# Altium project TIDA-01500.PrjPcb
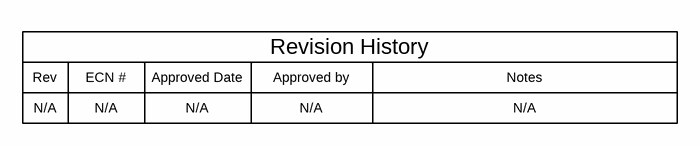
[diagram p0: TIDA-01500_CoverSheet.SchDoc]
CopyrightYear: 2017; PCB_Layout: Levan Bidzishvili; PCB_Rev: E1; PRJ_Customer: Public Release; PRJ_Engineer: Levan Bidzishvili; PRJ_Number: TIDA-01500; PRJ_Title: Automotive Multi Channel LED Driver for HVAC HMI; SCH_Rev: E1; TechSupport: http://www.ti.com/support; TID: N/A
3 sheets, 58 parts. Net scope: global (net labels, ports and power ports of the same name join across sheets).
Board file: TIDA-01500_PCB.PcbDoc
Sheets:
  TIDA-01500_CoverSheet.SchDoc
  TIDA-01500_BlankSheet.SchDoc
  TIDA-01500_EVM_Hardware.SchDoc

## Sheet TIDA-01500_CoverSheet.SchDoc
size 431 x 279 mm; Date: Not shown in title block; ApprovedBy: Not shown in title block; CheckedBy: Not shown in title block; Author: Not shown in title block; CompanyName: Not shown in title block; Engineer: Not shown in title block; Organization: Not shown in title block; Address1: Not shown in title block; Address2: Not shown in title block; Address3: Not shown in title block; Address4: Not shown in title block; DocumentNumber: 1; Revision: Use project parameter SCH_Rev; SheetNumber: 1; SheetTotal: 3; PageSetup: Record=PageOptions¦CenterHorizontal=True¦CenterVertical=True¦PrintScale=1.00¦XCorrection=1.00¦YCorrection=1.00¦PrintKind=0¦BorderSize=5000000¦LeftOffset=0¦BottomOffset=0¦Orientation=2¦PaperLength=1000¦PaperWidth=1000¦Scale=100¦PaperSource=15¦PrintQuality=600¦MediaType=1¦DitherType=10¦PaperKind=Letter¦PrintScaleMode=1

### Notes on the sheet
- Rev
- N/A
- ECN #
- Approved Date
- Approved by
- Revision History
- Notes

## Sheet TIDA-01500_BlankSheet.SchDoc
size 431 x 279 mm; Date: Not shown in title block; ApprovedBy: Not shown in title block; CheckedBy: Not shown in title block; Author: Not shown in title block; CompanyName: Not shown in title block; Engineer: Not shown in title block; Organization: Not shown in title block; Address1: Not shown in title block; Address2: Not shown in title block; Address3: Not shown in title block; Address4: Not shown in title block; DocumentNumber: 1; Revision: Use project parameter SCH_Rev; SheetNumber: 2; SheetTotal: 3; PageSetup: Record=PageOptions¦CenterHorizontal=True¦CenterVertical=True¦PrintScale=0.64¦XCorrection=1.00¦YCorrection=1.00¦PrintKind=0¦BorderSize=5000000¦LeftOffset=0¦BottomOffset=0¦Orientation=2¦PaperLength=1000¦PaperWidth=1000¦Scale=100¦PaperSource=15¦PrintQuality=600¦MediaType=1¦DitherType=10¦PrintScaleMode=1¦PaperKind=Letter
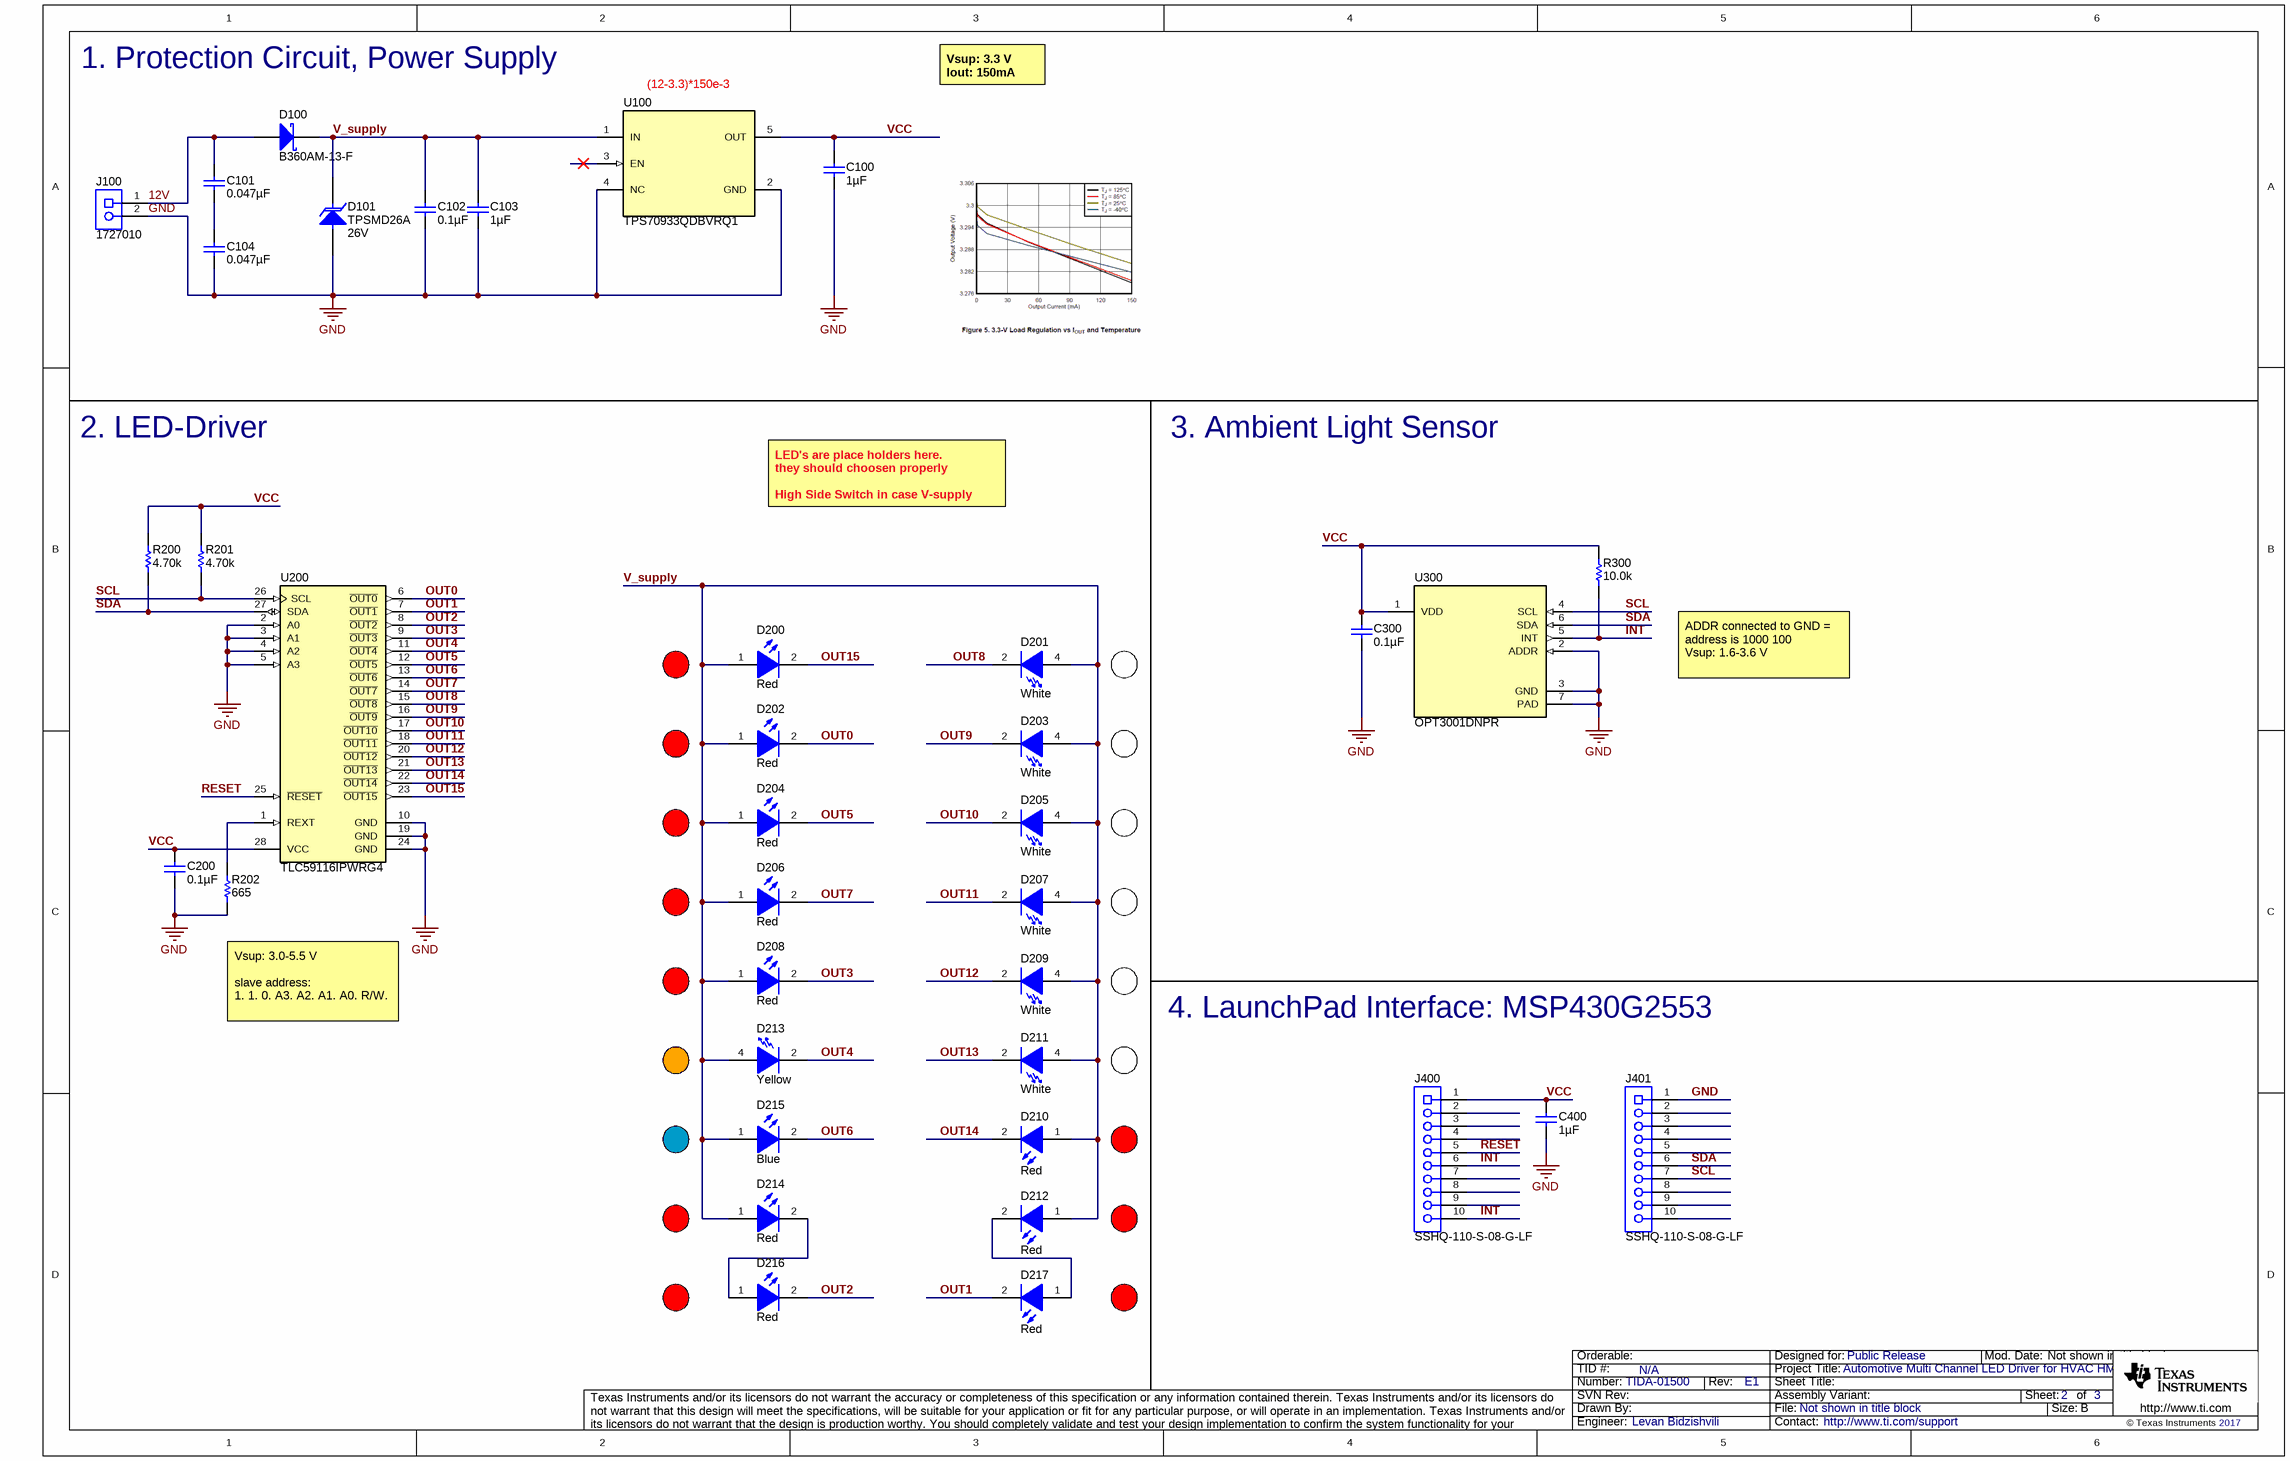
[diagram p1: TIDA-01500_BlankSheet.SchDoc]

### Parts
C100  ValueDisplayed: 1µF  [0805_HV]  (hidden comment: CGA4J3X7R1H105K125AB)
C101  ValueDisplayed: 0.047µF  [0805_HV]  (hidden comment: GCM21BR72A473KA37L)
C102  ValueDisplayed: 0.1µF  [0805_HV]  (hidden comment: GCM21BR71H104KA37K)
C103  ValueDisplayed: 1µF  [0805_HV]  (hidden comment: CGA4J3X7R1H105K125AB)
C104  ValueDisplayed: 0.047µF  [0805_HV]  (hidden comment: GCM21BR72A473KA37L)
C200  ValueDisplayed: 0.1µF  [0805_HV]  (hidden comment: GCM21BR71H104KA37K)
C300  ValueDisplayed: 0.1µF  [0603]  (hidden comment: CGJ3E2X7R1C104K080AA)
C400  ValueDisplayed: 1µF  [0805_HV]  (hidden comment: CGA4J3X7R1H105K125AB)
D100  B360AM-13-F  [SMA]
D101  TPSMD26A  value 26V  [SMC_265]
D200  value Red  [VLMR334_Red]  (hidden comment: VLMR334BACB-GS08)
D201  value White  [LED_PowerTOPLED_GF]  (hidden comment: LW-E6SG)
D202  value Red  [VLMR334_Red]  (hidden comment: VLMR334BACB-GS08)
D203  value White  [LED_PowerTOPLED_GF]  (hidden comment: LW-E6SG)
D204  value Red  [VLMR334_Red]  (hidden comment: VLMR334BACB-GS08)
D205  value White  [LED_PowerTOPLED_GF]  (hidden comment: LW-E6SG)
D206  value Red  [VLMR334_Red]  (hidden comment: VLMR334BACB-GS08)
D207  value White  [LED_PowerTOPLED_GF]  (hidden comment: LW-E6SG)
D208  value Red  [VLMR334_Red]  (hidden comment: VLMR334BACB-GS08)
D209  value White  [LED_PowerTOPLED_GF]  (hidden comment: LW-E6SG)
D210  value Red  [VLMR334_Red]  (hidden comment: VLMR334BACB-GS08)
D211  value White  [LED_PowerTOPLED_GF]  (hidden comment: LW-E6SG)
D212  value Red  [VLMR334_Red]  (hidden comment: VLMR334BACB-GS08)
D213  value Yellow  [LED_PowerTOPLED_GF]  (hidden comment: LY-E6SF)
D214  value Red  [VLMR334_Red]  (hidden comment: VLMR334BACB-GS08)
D215  value Blue  [LB_T673_Blue]  (hidden comment: LB T673-L2P1-25-Z)
D216  value Red  [VLMR334_Red]  (hidden comment: VLMR334BACB-GS08)
D217  value Red  [VLMR334_Red]  (hidden comment: VLMR334BACB-GS08)
J100  1727010  [PhoenixConact_1727010]
J400  SSHQ-110-S-08-G-LF  [Major_SSHQ-110-S-08]
J401  SSHQ-110-S-08-G-LF  [Major_SSHQ-110-S-08]
R200  ValueDisplayed: 4.70k  [0805_HV]  (hidden comment: ERJ-P06F4701V)
R201  ValueDisplayed: 4.70k  [0805_HV]  (hidden comment: ERJ-P06F4701V)
R202  ValueDisplayed: 665  [0805_HV]  (hidden comment: ERA-6AEB6650V)
R300  ValueDisplayed: 10.0k  [TNPW0603]  (hidden comment: TNPW060310K0BEEA)
U100  TPS70933QDBVRQ1  [DBV0005A_N]
U200  TLC59116IPWRG4  [PW0028A_N]
U300  OPT3001DNPR  [DNP0006A]

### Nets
GND: C100.2 C102.2 C103.2 C104.2 C200.2 C300.2 C400.2 D101.2(A) J100.2 J401.1 R202.1 U100.2(GND) U100.4(NC) U200.2(A0) U200.3(A1) U200.4(A2) U200.5(A3) U200.10(GND) U200.19(GND) U200.24(GND) U300.2(ADDR) U300.3(GND) U300.7(PAD)
12V: C101.1 D100.2(A) J100.1
INT: J400.6 J400.10 R300.2 U300.5(INT)
OUT0: D202.2(K) U200.6(~{OUT0})
OUT1: D217.2(K) U200.7(~{OUT1})
OUT2: D216.2(K) U200.8(~{OUT2})
OUT3: D208.2(K) U200.9(~{OUT3})
OUT4: D213.2(K) U200.11(~{OUT4})
OUT5: D204.2(K) U200.12(~{OUT5})
OUT6: D215.2(K) U200.13(~{OUT6})
OUT7: D206.2(K) U200.14(~{OUT7})
OUT8: D201.2(K) U200.15(~{OUT8})
OUT9: D203.2(K) U200.16(~{OUT9})
OUT10: D205.2(K) U200.17(~{OUT10})
OUT11: D207.2(K) U200.18(~{OUT11})
OUT12: D209.2(K) U200.20(~{OUT12})
OUT13: D211.2(K) U200.21(~{OUT13})
OUT14: D210.2(K) U200.22(~{OUT14})
OUT15: D200.2(K) U200.23(~{OUT15})
RESET: J400.5 U200.25(~{RESET})
SCL: J401.7 R201.1 U200.26(SCL) U300.4(SCL)
SDA: J401.6 R200.1 U200.27(SDA) U300.6(SDA)
V_supply: C102.1 C103.1 D100.1(K) D101.1(K) D200.1(A) D201.4(A) D202.1(A) D203.4(A) D204.1(A) D205.4(A) D206.1(A) D207.4(A) D208.1(A) D209.4(A) D210.1(A) D211.4(A) D212.1(A) D213.4(A) D214.1(A) D215.1(A) U100.1(IN)
VCC: C100.1 C200.1 C300.1 C400.1 J400.1 R200.2 R201.2 R300.1 U100.5(OUT) U200.28(VCC) U300.1(VDD)
NetC101_2: C101.2 C104.1
NetD212_2: D212.2(K) D217.1(A)
NetD214_2: D214.2(K) D216.1(A)
NetR202_2: R202.2 U200.1(REXT)

Not connected (* = marked no-connect by the designer): J400 2 3 4 7 8 9; J401 2 3 4 5 8 9 10; U100 3(EN)*

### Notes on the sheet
- 1. Protection Circuit, Power Supply
- (near U100) (12-3.3)*150e-3
- Vsup: 3.3 V
  Iout: 150mA
- standoff voltage should be above 24V because of jump-start condition. better would be 26V
  SMAJ26CAHE3/61 VISHAY
  TPS... littlefuse
- 2. LED-Driver
- 3. Ambient Light Sensor
- LED's are place holders here.
  they should choosen properly
  High Side Switch in case V-supply goes above 17V
- ADDR connected to GND = address is 1000 100
  Vsup: 1.6-3.6 V
- (near R202) Vsup: 3.0-5.5 V
  slave address:
  1. 1. 0. A3. A2. A1. A0. R/W.
- 4. LaunchPad Interface: MSP430G2553
- ToDo:
  1) LaunchPad supply
  2) some editional features like buttons
  3) high side switch to On/Off LED voltage in case Vsupply goes over 17V
  4) choosing the propper LED's

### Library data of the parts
C100 C103 C400 = CGA4J3X7R1H105K125AB: CAP, CERM, 1 µF, 50 V, +/- 10%, X7R, AEC-Q200 Grade 1, 0805; Manufacturer: TDK; Polarized: N; CompType: Capacitor; Value: 1uF; U/M: EA; Cap_F: 0.000001; Tolerance_%: 10; ESR_ohm: 0.008782; Value1: 0.008782 ohm; VDC_V: 50; Value2: 50V; IRMS_A: 2.20488; TaMin_C: -55; TaMax_C: 125; Cap_Case: 0805; SizeArea_mm2: 2.5; SizeAreaWB_mm2: 6.75; SizeX_mm: 2; SizeY_mm: 1.25; SizeZ_mm: 1.45; AEC Category: Q200; AEC Qualified: Y; AEC Grade: 1
C101 C104 = GCM21BR72A473KA37L: CAP, CERM, 0.047 µF, 100 V, +/- 10%, X7R, AEC-Q200 Grade 1, 0805; Manufacturer: MuRata; Polarized: N; CompType: Capacitor; Value: 0.047uF; U/M: EA; Cap_F: 0.000000047; Tolerance_%: 10; Value1: Unknown; VDC_V: 100; Value2: 100V; TaMin_C: -55; TaMax_C: 125; Cap_Case: 0805; SizeArea_mm2: 2.5; SizeAreaWB_mm2: 6.75; SizeX_mm: 2; SizeY_mm: 1.25; SizeZ_mm: 1.45; AEC Category: Q200; AEC Qualified: Y; AEC Grade: 1
C102 C200 = GCM21BR71H104KA37K: CAP, CERM, 0.1 µF, 50 V, +/- 10%, X7R, AEC-Q200 Grade 1, 0805; Manufacturer: MuRata; Polarized: N; CompType: Capacitor; Value: 0.1uF; U/M: EA; Cap_F: 0.0000001; Tolerance_%: 10; Value1: Unknown; VDC_V: 50; Value2: 50V; TaMin_C: -55; TaMax_C: 125; Cap_Case: 0805; SizeArea_mm2: 2.5; SizeAreaWB_mm2: 6.75; SizeX_mm: 2; SizeY_mm: 1.25; SizeZ_mm: 1.45; AEC Category: Q200; AEC Qualified: Y; AEC Grade: 1
C300 = CGJ3E2X7R1C104K080AA: CAP, CERM, 0.1 µF, 16 V,+/- 10%, X7R, AEC-Q200 Grade 1, 0603; Manufacturer: TDK; Polarized: N; CompType: Capacitor; Value: 0.1uF; U/M: EA; Cap_F: 0.0000001; Tolerance_%: 10; VDC_V: 16; Value2: 16V; TaMin_C: -55; TaMax_C: 125; SizeArea_mm2: 1.28; SizeAreaWB_mm2: 4.68; SizeX_mm: 1.6; SizeY_mm: 0.8; SizeZ_mm: 1; AEC Category: Q200; AEC Qualified: Y; Green_Lifecycle: NRND; Green_REACh: Passed
D100 = B360AM-13-F: Diode, Schottky, 60 V, 3 A, AEC-Q101, SMA; Manufacturer: Diodes Inc.; U/M: EA; Vf_V: 0.7; Value: 60V; Value1: 3A; Value2: 0.7V; Io_A: 3; Vr_V: 60; TJmax_C: 150; SizeAreaWB_mm2: 37.3428; SizeArea_mm2: 16.3228; SizeX_mm: 5.59; SizeY_mm: 2.92; SizeZ_mm: 2.87; AEC Category: Q101; AEC Qualified: Y; Green_Lifecycle: Not Set; Green_REACh: Incomplete
D101 = TPSMD26A: Diode, TVS, Uni, 26 V, 42.1 Vc, AEC-Q101, SMC; Manufacturer: Littelfuse; U/M: EA; Power_W: 6.5; Vr_V: 26; Value1: 6.5W; RJA_CperW: 75; SizeAreaWB_mm2: 78.5757; SizeArea_mm2: 46.8857; SizeX_mm: 7.94; SizeY_mm: 5.905; SizeZ_mm: 2.62; AEC Category: Q101; AEC Qualified: Y
D200 D202 D204 D206 D208 D210 D212 D214 D216 D217 = VLMR334BACB-GS08: LED, Red, SMD; Manufacturer: Vishay-Semiconductor; Type: AlInGaP; Vf_V: 2.2; Value2: 2.2V; Io_A: 0.05; Vr_V: 5; Ir_A: 1e-005; Tjmax_C: 125; Power_TotalModule: 0.2; Value1: 0.2W; Angle: 120; SizeAreaWB_mm2: 17.1; SizeArea_mm2: 9.8; SizeX_mm: 3.5; SizeY_mm: 2.8; SizeZ_mm: 1.85; U/M: EA
D201 D203 D205 D207 D209 D211 = LW-E6SG: LED, White, SMD; Manufacturer: OSRAM; ColorTemperature: 5600K; Vf_V: 3.4; Value2: 3.4V; Io_A: 0.03; Vr_V: 5; RJC_CperW: 180; Tjmax_C: 125; Power_TotalModule: 0.102; Value1: 0.102W; NumParallelLEDs: 1; LuminousFlux_PhiV: 4; Angle: 120; FamilyName: Power TOPLED&#174;; SizeAreaWB_mm2: 17.1; SizeArea_mm2: 9.8; SizeX_mm: 3.5; SizeY_mm: 2.8; SizeZ_mm: 1.9; U/M: EA
D213 = LY-E6SF: LED, Yellow, SMD; Manufacturer: OSRAM; Vf_V: 2.15; Value2: 2.15V; Io_A: 0.05; Vr_V: 12; RJC_CperW: 130; Tjmax_C: 125; Power_TotalModule: 0.1075; Value1: 0.1075W; LambdaP: 597; LambdaD: 590; NumParallelLEDs: 1; LuminousFlux_PhiV: 4.98; Angle: 120; FamilyName: Power TOPLED&#174;; SizeAreaWB_mm2: 17.1; SizeArea_mm2: 9.8; SizeX_mm: 3.5; SizeY_mm: 2.8; SizeZ_mm: 1.9; U/M: EA
D215 = LB T673-L2P1-25-Z: LED, Blue, SMD; Manufacturer: OSRAM; Type: InGaN; Vf_V: 3.1; Value2: 3.1V; Io_A: 0.02; Vr_V: 5; Ir_A: 1e-005; Tjmax_C: 110; Value1: W; Angle: 120; SizeAreaWB_mm2: 17.1; SizeArea_mm2: 9.8; SizeX_mm: 2.8; SizeY_mm: 3.5; SizeZ_mm: 2.1; U/M: EA
J100 = 1727010: Conn Term Block, 2POS, 3.81mm, TH; Manufacturer: Phoenix Contact; SymbolCreator: a0412235; CompType: Terminal Block
J400 J401 = SSHQ-110-S-08-G-LF: Receptacle, 2.54mm, 10x1, TH; Manufacturer: Major League Electronics; SymbolCreator: a0411947; Pitch_mm: 2.54; Gender: Female; Row_Count: 1; ContactFinish: Gold; Current_A: 3; Voltage_V: 600
R200 R201 = ERJ-P06F4701V: RES, 4.70 k, 1%, 0.5 W, AEC-Q200 Grade 0, 0805; Manufacturer: Panasonic; CompType: Resistor; Value: 4.70k; Res_ohm: 4700; Value_Code: 4k70; Tolerance_%: 1; Power_W: 0.5; Value2: 0.5W; VDC_V: 400; TempCo: 100 ppm/C; SizeArea_mm2: 2.5; SizeX_mm: 2; SizeY_mm: 1.25; SizeZ_mm: 1.45; U/M: EA; AEC Category: Q200; AEC Qualified: Y; AEC Grade: 0
R202 = ERA-6AEB6650V: RES, 665, 0.1%, 0.125 W, AEC-Q200 Grade 0, 0805; Manufacturer: Panasonic; CompType: Resistor; Value: 665; Value_Code: 665R; Tolerance_%: 0.1; Power_W: 0.125; Value2: 0.125W; VDC_V: 100; TempCo: 25 ppm/C; SizeArea_mm2: 2.5; SizeX_mm: 2; SizeY_mm: 1.25; SizeZ_mm: 1.45; EIA_Code: E192; U/M: EA; AEC Category: Q200; AEC Qualified: Y; AEC Grade: 0
R300 = TNPW060310K0BEEA: RES, 10.0 k, 0.1%, 0.1 W, AEC-Q200 Grade 1, 0603; Manufacturer: Vishay-Dale; CompType: Resistor; Value: 10.0k; Res_ohm: 10000; Value_Code: 10k0; Tolerance_%: 0.1; Value2: 0.1W; VDC_V: 75; TempCo: 25 ppm/C; SizeArea_mm2: 1.36; SizeX_mm: 1.6; SizeY_mm: 0.85; SizeZ_mm: 0.55; EIA_Code: E192; U/M: EA; AEC Category: Q200; AEC Qualified: Y; AEC Grade: 1
U100 = TPS70933QDBVRQ1: 150-mA, 30-V, 1-uA IQ Voltage Regulator with Enable, DBV0005A (SOT-23-5); Manufacturer: Texas Instruments; SymbolCreator: Altium; SizeArea_mm2: 8.12; SizeAreaWB_mm2: 14.82; SizeX_mm: 2.8; SizeY_mm: 2.9; SizeZ_mm: 1.45; CompType: IC; U/M: EA
U200 = TLC59116IPWRG4: 16-Bit Fast-Mode Plus (FM+) I2C Bus Constant-Current LED Sink Driver, 3 to 5.5 V, -40 to 85 degC, 28-pin SOP (PW28), Green (RoHS & no Sb/Br); Manufacturer: Texas Instruments; Alternate PartNumber: Equivalent; Rating: Catalog; SubFamily: LED Driver; Vin(Max)(V): 5.5; Vin(Min)(V): 3
U300 = OPT3001DNPR: Digital Ambient Light Sensor (ALS) with High Precision Human Eye Response, DNP0006A (USON-6); Alternate PartNumber: OPT3001DNPT; Manufacturer: Texas Instruments; SymbolCreator: a0411947; SizeArea_mm2: 4; SizeAreaWB_mm2: 9; SizeX_mm: 2; SizeZ_mm: 0.65; CompType: IC; U/M: EA

## Sheet TIDA-01500_EVM_Hardware.SchDoc
size 431 x 279 mm; Date: Not shown in title block; ApprovedBy: Not shown in title block; CheckedBy: Not shown in title block; Author: Not shown in title block; CompanyName: Not shown in title block; Engineer: Not shown in title block; Organization: Not shown in title block; Address1: Not shown in title block; Address2: Not shown in title block; Address3: Not shown in title block; Address4: Not shown in title block; DocumentNumber: 1; Revision: Use project parameter SCH_Rev; SheetNumber: 3; SheetTotal: 3; PageSetup: Record=PageOptions¦CenterHorizontal=True¦CenterVertical=True¦PrintScale=1.00¦XCorrection=1.00¦YCorrection=1.00¦PrintKind=0¦BorderSize=5000000¦LeftOffset=0¦BottomOffset=0¦Orientation=2¦PaperLength=1000¦PaperWidth=1000¦Scale=100¦PaperSource=15¦PrintQuality=600¦MediaType=1¦DitherType=10¦PaperKind=Letter¦PrintScaleMode=1
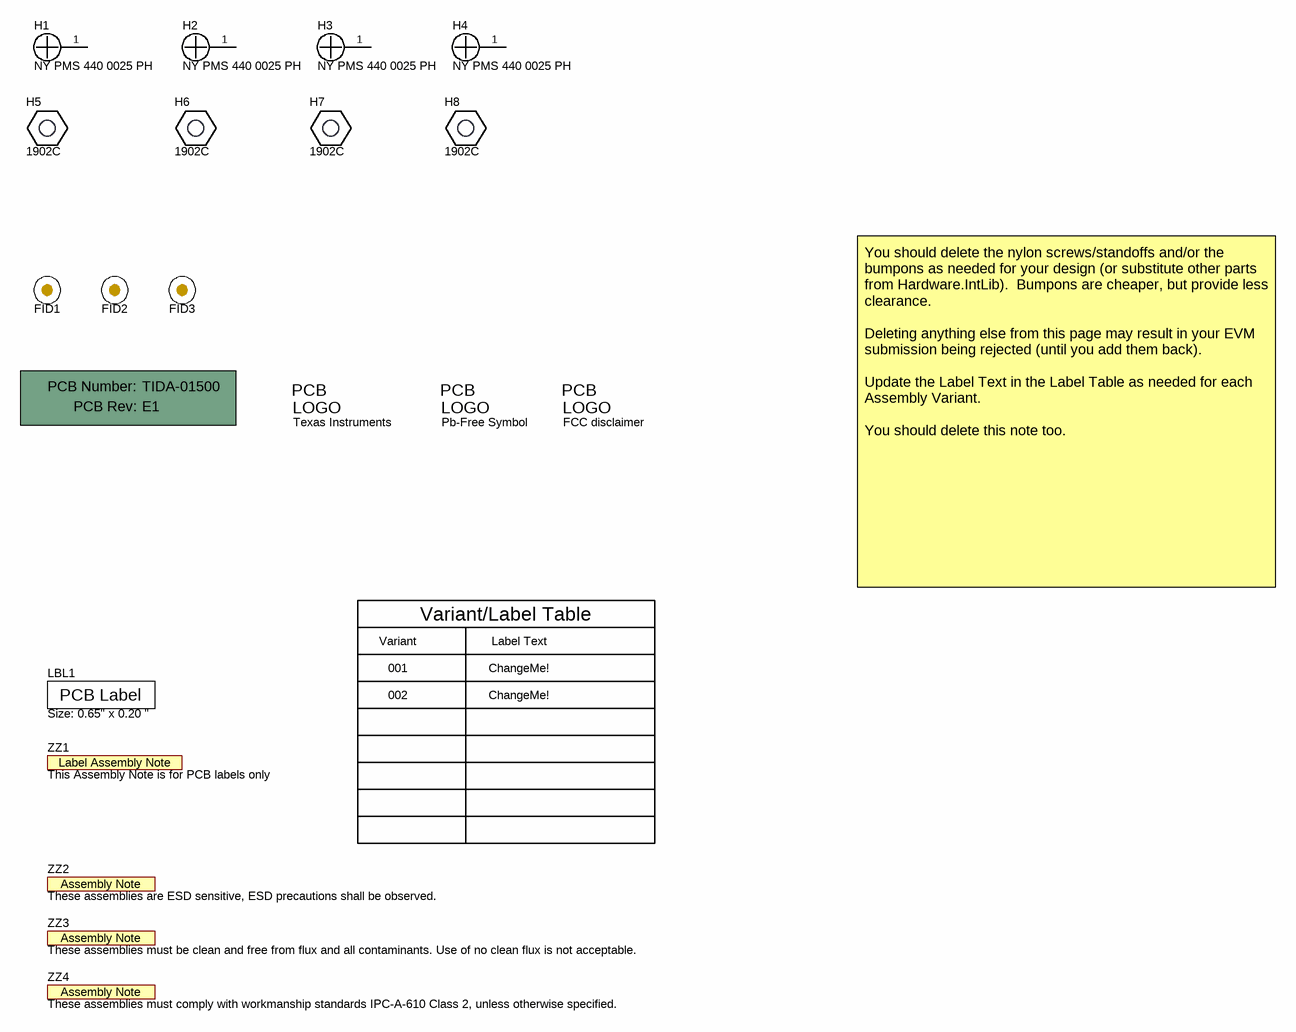
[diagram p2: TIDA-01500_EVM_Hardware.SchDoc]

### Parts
!PCB  Printed Circuit Board  (value not drawn)  (mechanical)
FID1  Fiducial  [Fiducial10-20]  (value not drawn)
FID2  Fiducial  [Fiducial10-20]  (value not drawn)
FID3  Fiducial  [Fiducial10-20]  (value not drawn)
H1  NY PMS 440 0025 PH  [NY PMS 440 0025 PH]
H2  NY PMS 440 0025 PH  [NY PMS 440 0025 PH]
H3  NY PMS 440 0025 PH  [NY PMS 440 0025 PH]
H4  NY PMS 440 0025 PH  [NY PMS 440 0025 PH]
H5  1902C  [Keystone_1902C]
H6  1902C  [Keystone_1902C]
H7  1902C  [Keystone_1902C]
H8  1902C  [Keystone_1902C]
LBL1  Size: 0.65" x 0.20 "  [Label_650x200]
Logo1  Texas Instruments  [TI_Stacked_Overlay_Small]  (no BOM)
Logo2  Pb-Free Symbol  [Pb-Free_Overlay_Small]  (no BOM)
Logo3  FCC disclaimer  [FCC_disclaimer]  (no BOM)
ZZ1  This Assembly Note is for PCB labels only  [AssemblyNoteLabel]  (no BOM)
ZZ2  These assemblies are ESD sensitive, ESD precautions shall be observed.  [AssemblyNote]  (no BOM)
ZZ3  These assemblies must be clean and free from flux and all contaminants. Use of no clean flux is not acceptable.  [AssemblyNote]  (no BOM)
ZZ4  These assemblies must comply with workmanship standards IPC-A-610 Class 2, unless otherwise specified.  [AssemblyNote]  (no BOM)

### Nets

Not connected (* = marked no-connect by the designer): H1 1; H2 1; H3 1; H4 1

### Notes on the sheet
- Variant
- Variant/Label Table
- Label Text
- You should delete the nylon screws/standoffs and/or the bumpons as needed for your design (or substitute other parts from Hardware.IntLib).  Bumpons are cheaper, but provide less clearance.
  Deleting anything else from this page may result in your EVM submission being rejected (until you add them back).
  Update the Label Text in the Label Table as needed for each Assembly Variant.
  You should delete this note too.
- 001
- 002
- ChangeMe!

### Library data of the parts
!PCB = PCB: Manufacturer: Any; PartNumber: TIDA-01500; SymbolCreator: a0412235
FID1-FID3 = Fiducial: Fiducial mark.  There is nothing to buy or mount.; SymbolCreator: codlsc
H1-H4 = NY PMS 440 0025 PH: Machine Screw, Round, #4-40 x 1/4, Nylon, Philips panhead; Manufacturer: B&F Fastener Supply; CompType: Hardware; SymbolCreator: codlsc; U/M: EA
H5-H8 = 1902C: Standoff, Hex, 0.5"L #4-40 Nylon; Manufacturer: Keystone; CompType: Hardware
LBL1 = THT-14-423-10: Thermal Transfer Printable Labels, 0.650" W x 0.200" H - 10,000 per roll; Manufacturer: Brady; SymbolCreator: a0412235; CompType: Label
Logo1 = TI_Logo: Texas Instrument Corporate Signature; SymbolCreator: codlsc
Logo2 = Pb-Free: SymbolCreator: a0412235
Logo3 = FCC_disclaimer: SymbolCreator: codlsc
ZZ1 = AssemblyNoteLabel: SymbolCreator: a0412235
ZZ2-ZZ4 = AssemblyNote: SymbolCreator: codlsc

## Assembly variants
001: not fitted FID1 FID2 FID3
